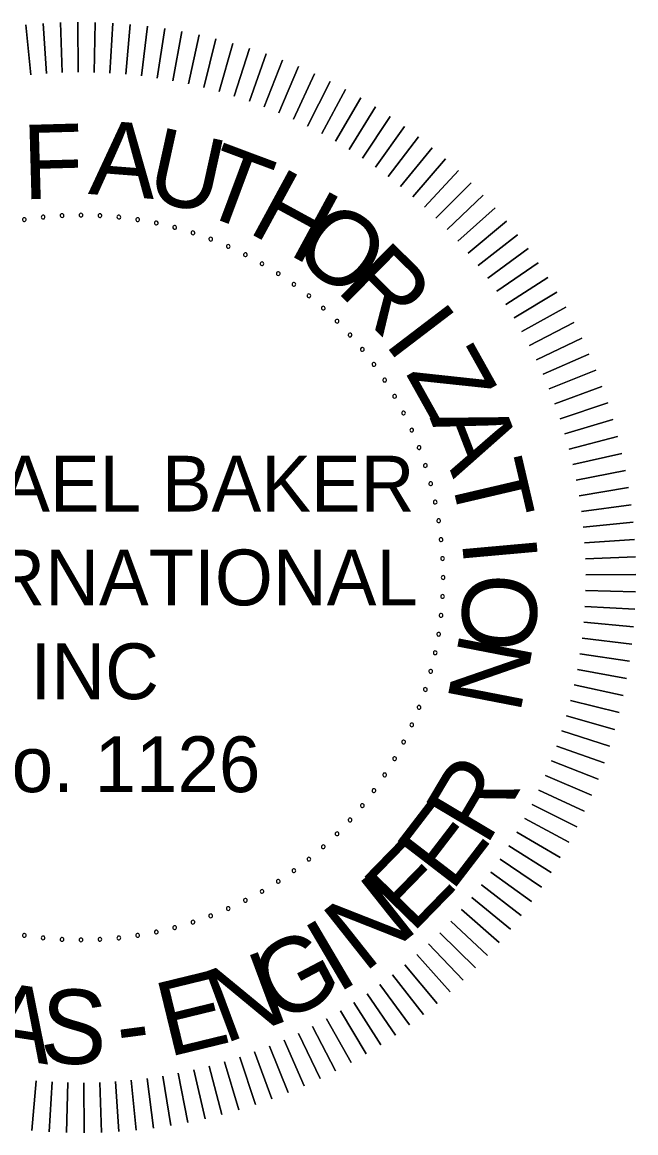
# Model space of a CAD drawing. Extents: x -24122 to 24238, y -8840 to 11381.
# Drawn here: x 11660 to 13036, y -8840 to -6351 of the extents above; entities that cross this region are included whole.
import ezdxf

# ---------------------------------------------------------------- set-up
doc = ezdxf.new("R2010")
doc.units = 0
doc.layers.add('G-ANNO-TEXT', color=7, linetype='Continuous')

msp = doc.modelspace()

# ---------------------------------------------------------------- linework, layer by layer
at = {"layer": 'G-ANNO-TEXT'}
for points in [[(11679.1, -6468.9), (11667.9, -6357.3)], [(11667.9, -6357.3), (11679.1, -6468.9)], [(11714.5, -6466), (11706.8, -6354)], [(11706.8, -6354), (11714.5, -6466)], [(11750, -6464.1), (11745.9, -6351.9)], [(11745.9, -6351.9), (11750, -6464.1)], [(11785.6, -6463.3), (11785, -6351.1)], [(11785, -6351.1), (11785.6, -6463.3)], [(11821.1, -6463.7), (11824, -6351.5)], [(11824, -6351.5), (11821.1, -6463.7)], [(11856.7, -6465.2), (11863.1, -6353.1)], [(11863.1, -6353.1), (11856.7, -6465.2)], [(11892.2, -6467.8), (11902.1, -6356)], [(11902.1, -6356), (11892.2, -6467.8)], [(11927.5, -6471.5), (11941, -6360)], [(11941, -6360), (11927.5, -6471.5)], [(11962.8, -6476.3), (11979.7, -6365.3)], [(11979.7, -6365.3), (11962.8, -6476.3)], [(11997.8, -6482.2), (12018.3, -6371.8)], [(12018.3, -6371.8), (11997.8, -6482.2)], [(12032.7, -6489.2), (12056.6, -6379.6)], [(12056.6, -6379.6), (12032.7, -6489.2)], [(12067.3, -6497.3), (12094.6, -6388.5)], [(12094.6, -6388.5), (12067.3, -6497.3)], [(12101.7, -6506.5), (12132.4, -6398.6)], [(12132.4, -6398.6), (12101.7, -6506.5)], [(12135.7, -6516.8), (12169.8, -6409.9)], [(12169.8, -6409.9), (12135.7, -6516.8)], [(12169.5, -6528.1), (12206.9, -6422.3)], [(12206.9, -6422.3), (12169.5, -6528.1)], [(12202.8, -6540.5), (12243.5, -6435.9)], [(12243.5, -6435.9), (12202.8, -6540.5)], [(12235.7, -6553.9), (12279.7, -6450.7)], [(12279.7, -6450.7), (12235.7, -6553.9)], [(12268.2, -6568.4), (12315.5, -6466.6)], [(12315.5, -6466.6), (12268.2, -6568.4)], [(12300.3, -6583.9), (12350.7, -6483.6)], [(12350.7, -6483.6), (12300.3, -6583.9)], [(12331.8, -6600.3), (12385.3, -6501.7)], [(12385.3, -6501.7), (12331.8, -6600.3)], [(12362.8, -6617.8), (12419.4, -6520.9)], [(12419.4, -6520.9), (12362.8, -6617.8)], [(12393.2, -6636.2), (12452.8, -6541.1)], [(12452.8, -6541.1), (12393.2, -6636.2)], [(12423, -6655.6), (12485.6, -6562.4)], [(12485.6, -6562.4), (12423, -6655.6)], [(12452.3, -6675.8), (12517.7, -6584.7)], [(12517.7, -6584.7), (12452.3, -6675.8)], [(12480.8, -6697), (12549.1, -6608)], [(12549.1, -6608), (12480.8, -6697)], [(12508.7, -6719.1), (12579.8, -6632.3)], [(12579.8, -6632.3), (12508.7, -6719.1)], [(12535.9, -6742.1), (12609.6, -6657.5)], [(12609.6, -6657.5), (12535.9, -6742.1)], [(12638.7, -6683.6), (12562.3, -6765.9)], [(12562.3, -6765.9), (12638.7, -6683.6)], [(12666.9, -6710.7), (12588, -6790.5)], [(12588, -6790.5), (12666.9, -6710.7)], [(12694.3, -6738.6), (12612.9, -6815.9)], [(12612.9, -6815.9), (12694.3, -6738.6)], [(12720.7, -6767.4), (12637, -6842)], [(12637, -6842), (12720.7, -6767.4)], [(12746.3, -6796.9), (12660.2, -6869)], [(12660.2, -6869), (12746.3, -6796.9)], [(12770.9, -6827.3), (12682.6, -6896.6)], [(12682.6, -6896.6), (12770.9, -6827.3)], [(12794.5, -6858.4), (12704.1, -6924.9)], [(12704.1, -6924.9), (12794.5, -6858.4)], [(12817.2, -6890.3), (12724.7, -6953.9)], [(12724.7, -6953.9), (12817.2, -6890.3)], [(12838.9, -6922.9), (12744.4, -6983.5)], [(12744.4, -6983.5), (12838.9, -6922.9)], [(12859.5, -6956.1), (12763.2, -7013.7)], [(12763.2, -7013.7), (12859.5, -6956.1)], [(12879, -6989.9), (12781, -7044.5)], [(12781, -7044.5), (12879, -6989.9)], [(12897.5, -7024.4), (12797.8, -7075.9)], [(12797.8, -7075.9), (12897.5, -7024.4)], [(12914.9, -7059.4), (12813.6, -7107.7)], [(12813.6, -7107.7), (12914.9, -7059.4)], [(12931.2, -7094.9), (12828.4, -7140.1)], [(12828.4, -7140.1), (12931.2, -7094.9)], [(12946.3, -7131), (12842.2, -7172.8)], [(12842.2, -7172.8), (12946.3, -7131)], [(12960.4, -7167.4), (12855, -7206)], [(12855, -7206), (12960.4, -7167.4)], [(12973.2, -7204.4), (12866.7, -7239.6)], [(12866.7, -7239.6), (12973.2, -7204.4)], [(12984.9, -7241.7), (12877.3, -7273.6)], [(12877.3, -7273.6), (12984.9, -7241.7)], [(12995.5, -7279.3), (12886.9, -7307.8)], [(12886.9, -7307.8), (12995.5, -7279.3)], [(13004.8, -7317.3), (12895.4, -7342.4)], [(12895.4, -7342.4), (13004.8, -7317.3)], [(13012.9, -7355.5), (12902.8, -7377.1)], [(12902.8, -7377.1), (13012.9, -7355.5)], [(13019.9, -7394), (12909.1, -7412.2)], [(12909.1, -7412.2), (13019.9, -7394)], [(13025.6, -7432.6), (12914.3, -7447.3)], [(12914.3, -7447.3), (13025.6, -7432.6)], [(13030.1, -7471.5), (12918.4, -7482.7)], [(12918.4, -7482.7), (13030.1, -7471.5)], [(13033.4, -7510.4), (12921.4, -7518.1)], [(12921.4, -7518.1), (13033.4, -7510.4)], [(13035.5, -7549.5), (12923.3, -7553.6)], [(12923.3, -7553.6), (13035.5, -7549.5)], [(13036.3, -7588.6), (12924.1, -7589.2)], [(12924.1, -7589.2), (13036.3, -7588.6)], [(13035.9, -7627.6), (12923.7, -7624.7)], [(12923.7, -7624.7), (13035.9, -7627.6)], [(13034.3, -7666.7), (12922.2, -7660.3)], [(12922.2, -7660.3), (13034.3, -7666.7)], [(13031.4, -7705.7), (12919.6, -7695.8)], [(12919.6, -7695.8), (13031.4, -7705.7)], [(13027.3, -7744.6), (12915.9, -7731.1)], [(12915.9, -7731.1), (13027.3, -7744.6)], [(13022, -7783.3), (12911.1, -7766.4)], [(12911.1, -7766.4), (13022, -7783.3)], [(13015.5, -7821.9), (12905.2, -7801.4)], [(12905.2, -7801.4), (13015.5, -7821.9)], [(13007.8, -7860.2), (12898.2, -7836.3)], [(12898.2, -7836.3), (13007.8, -7860.2)], [(12998.9, -7898.2), (12890.1, -7870.9)], [(12890.1, -7870.9), (12998.9, -7898.2)], [(12988.8, -7936), (12880.9, -7905.3)], [(12880.9, -7905.3), (12988.8, -7936)], [(12977.5, -7973.4), (12870.6, -7939.4)], [(12870.6, -7939.4), (12977.5, -7973.4)], [(12965.1, -8010.5), (12859.3, -7973.1)], [(12859.3, -7973.1), (12965.1, -8010.5)], [(12951.5, -8047.1), (12846.9, -8006.4)], [(12846.9, -8006.4), (12951.5, -8047.1)], [(12936.7, -8083.3), (12833.4, -8039.3)], [(12833.4, -8039.3), (12936.7, -8083.3)], [(12920.8, -8119.1), (12819, -8071.8)], [(12819, -8071.8), (12920.8, -8119.1)], [(12903.8, -8154.3), (12803.5, -8103.9)], [(12803.5, -8103.9), (12903.8, -8154.3)], [(12885.7, -8188.9), (12787.1, -8135.4)], [(12787.1, -8135.4), (12885.7, -8188.9)], [(12866.5, -8223), (12769.6, -8166.4)], [(12769.6, -8166.4), (12866.5, -8223)], [(12846.3, -8256.4), (12751.2, -8196.8)], [(12751.2, -8196.8), (12846.3, -8256.4)], [(12825, -8289.2), (12731.8, -8226.6)], [(12731.8, -8226.6), (12825, -8289.2)], [(12802.7, -8321.3), (12711.5, -8255.9)], [(12711.5, -8255.9), (12802.7, -8321.3)], [(12779.4, -8352.7), (12690.3, -8284.4)], [(12690.3, -8284.4), (12779.4, -8352.7)], [(12755.1, -8383.4), (12668.3, -8312.3)], [(12668.3, -8312.3), (12755.1, -8383.4)], [(12729.9, -8413.2), (12645.3, -8339.5)], [(12645.3, -8339.5), (12729.9, -8413.2)], [(12703.8, -8442.3), (12621.5, -8365.9)], [(12621.5, -8365.9), (12703.8, -8442.3)], [(12676.7, -8470.5), (12596.9, -8391.6)], [(12596.9, -8391.6), (12676.7, -8470.5)], [(12648.8, -8497.9), (12571.5, -8416.5)], [(12571.5, -8416.5), (12648.8, -8497.9)], [(12620, -8524.3), (12545.3, -8440.6)], [(12545.3, -8440.6), (12620, -8524.3)], [(12560.1, -8574.5), (12490.8, -8486.2)], [(12490.8, -8486.2), (12560.1, -8574.5)], [(12590.4, -8549.9), (12518.4, -8463.8)], [(12518.4, -8463.8), (12590.4, -8549.9)], [(12528.9, -8598.2), (12462.5, -8507.7)], [(12462.5, -8507.7), (12528.9, -8598.2)], [(12497.1, -8620.8), (12433.5, -8528.3)], [(12433.5, -8528.3), (12497.1, -8620.8)], [(12464.5, -8642.5), (12403.9, -8548)], [(12403.9, -8548), (12464.5, -8642.5)], [(12397.5, -8682.6), (12342.8, -8584.6)], [(12342.8, -8584.6), (12397.5, -8682.6)], [(12431.3, -8663.1), (12373.6, -8566.8)], [(12373.6, -8566.8), (12431.3, -8663.1)], [(12363, -8701.1), (12311.5, -8601.4)], [(12311.5, -8601.4), (12363, -8701.1)], [(12292.5, -8734.8), (12247.3, -8632)], [(12247.3, -8632), (12292.5, -8734.8)], [(12328, -8718.5), (12279.7, -8617.2)], [(12279.7, -8617.2), (12328, -8718.5)], [(12219.9, -8764), (12181.3, -8658.6)], [(12181.3, -8658.6), (12219.9, -8764)], [(12256.4, -8749.9), (12214.5, -8645.8)], [(12214.5, -8645.8), (12256.4, -8749.9)], [(12145.7, -8788.5), (12113.8, -8680.9)], [(12113.8, -8680.9), (12145.7, -8788.5)], [(12183, -8776.8), (12147.8, -8670.3)], [(12147.8, -8670.3), (12183, -8776.8)], [(12031.9, -8816.5), (12010.2, -8706.4)], [(12010.2, -8706.4), (12031.9, -8816.5)], [(12070.1, -8808.4), (12045, -8699)], [(12045, -8699), (12070.1, -8808.4)], [(12108.1, -8799.1), (12079.6, -8690.5)], [(12079.6, -8690.5), (12108.1, -8799.1)], [(11681.7, -8835), (11691.6, -8723.2)], [(11691.6, -8723.2), (11681.7, -8835)], [(11720.7, -8837.9), (11727.1, -8725.8)], [(11727.1, -8725.8), (11720.7, -8837.9)], [(11759.7, -8839.5), (11762.6, -8727.3)], [(11762.6, -8727.3), (11759.7, -8839.5)], [(11798.8, -8839.9), (11798.2, -8727.7)], [(11798.2, -8727.7), (11798.8, -8839.9)], [(11837.9, -8839.1), (11833.8, -8726.9)], [(11833.8, -8726.9), (11837.9, -8839.1)], [(11876.9, -8837), (11869.3, -8725)], [(11869.3, -8725), (11876.9, -8837)], [(11915.9, -8833.7), (11904.7, -8722)], [(11904.7, -8722), (11915.9, -8833.7)], [(11954.7, -8829.2), (11940, -8717.9)], [(11940, -8717.9), (11954.7, -8829.2)], [(11993.4, -8823.5), (11975.2, -8712.7)], [(11975.2, -8712.7), (11993.4, -8823.5)]]:
    msp.add_lwpolyline(points, dxfattribs=at)
for centre, start, end in [((11664.8, -6793.3), 9, 189), ((11664.8, -6793.3), 189, 9), ((11707, -6787.8), 6, 186), ((11707, -6787.8), 186, 6), ((11749.4, -6784.5), 3, 183), ((11749.4, -6784.5), 183, 3), ((11791.9, -6783.3), 0, 180), ((11791.9, -6783.3), 180, 0), ((11834.4, -6784.5), 357, 177), ((11834.4, -6784.5), 177, 357), ((11876.8, -6787.8), 354, 174), ((11876.8, -6787.8), 174, 354), ((11918.9, -6793.3), 351, 171), ((11918.9, -6793.3), 171, 351), ((11960.7, -6801.1), 168, 348), ((11960.7, -6801.1), 348, 168), ((12002.1, -6811), 165, 345), ((12002.1, -6811), 345, 165), ((12042.9, -6823.1), 342, 162), ((12042.9, -6823.1), 162, 342), ((12082.9, -6837.3), 159, 339), ((12082.9, -6837.3), 339, 159), ((12122.2, -6853.6), 156, 336), ((12122.2, -6853.6), 336, 156), ((12160.6, -6871.9), 333, 153), ((12160.6, -6871.9), 153, 333), ((12198, -6892.2), 150, 330), ((12198, -6892.2), 330, 150), ((12234.2, -6914.4), 147, 327), ((12234.2, -6914.4), 327, 147), ((12269.3, -6938.5), 144, 324), ((12269.3, -6938.5), 324, 144), ((12303, -6964.3), 141, 321), ((12303, -6964.3), 321, 141), ((12335.3, -6991.9), 138, 318), ((12335.3, -6991.9), 318, 138), ((12366.2, -7021.2), 135, 315), ((12366.2, -7021.2), 315, 135), ((12395.4, -7052.1), 132, 312), ((12395.4, -7052.1), 312, 132), ((12423, -7084.4), 129, 309), ((12423, -7084.4), 309, 129), ((12448.9, -7118.1), 126, 306), ((12448.9, -7118.1), 306, 126), ((12473, -7153.2), 123, 303), ((12473, -7153.2), 303, 123), ((12495.2, -7189.4), 120, 300), ((12495.2, -7189.4), 300, 120), ((12515.5, -7226.8), 117, 297), ((12515.5, -7226.8), 297, 117), ((12533.8, -7265.2), 114, 294), ((12533.8, -7265.2), 294, 114), ((12550.1, -7304.4), 111, 291), ((12550.1, -7304.4), 291, 111), ((12564.3, -7344.5), 108, 288), ((12564.3, -7344.5), 288, 108), ((12576.4, -7385.3), 105, 285), ((12576.4, -7385.3), 285, 105), ((12586.3, -7426.6), 102, 282), ((12586.3, -7426.6), 282, 102), ((12594, -7468.4), 99, 279), ((12594, -7468.4), 279, 99), ((12599.6, -7510.6), 96, 276), ((12599.6, -7510.6), 276, 96), ((12602.9, -7553), 93, 273), ((12602.9, -7553), 273, 93), ((12604, -7595.5), 90, 270), ((12604, -7595.5), 270, 90), ((12602.9, -7638), 87, 267), ((12602.9, -7638), 267, 87), ((12599.6, -7680.4), 84, 264), ((12599.6, -7680.4), 264, 84), ((12594, -7722.5), 81, 261), ((12594, -7722.5), 261, 81), ((12586.3, -7764.3), 78, 258), ((12586.3, -7764.3), 258, 78), ((12576.4, -7805.7), 75, 255), ((12576.4, -7805.7), 255, 75), ((12564.3, -7846.5), 72, 252), ((12564.3, -7846.5), 252, 72), ((12550.1, -7886.5), 69, 249), ((12550.1, -7886.5), 249, 69), ((12533.8, -7925.8), 66, 246), ((12533.8, -7925.8), 246, 66), ((12515.5, -7964.2), 63, 243), ((12515.5, -7964.2), 243, 63), ((12495.2, -8001.6), 60, 240), ((12495.2, -8001.6), 240, 60), ((12473, -8037.8), 57, 237), ((12473, -8037.8), 237, 57), ((12448.9, -8072.9), 54, 234), ((12448.9, -8072.9), 234, 54), ((12423, -8106.6), 51, 231), ((12423, -8106.6), 231, 51), ((12395.4, -8138.9), 48, 228), ((12395.4, -8138.9), 228, 48), ((12366.2, -8169.8), 45, 225), ((12366.2, -8169.8), 225, 45), ((12335.3, -8199), 42, 222), ((12335.3, -8199), 222, 42), ((12303, -8226.6), 39, 219), ((12303, -8226.6), 219, 39), ((12269.3, -8252.5), 36, 216), ((12269.3, -8252.5), 216, 36), ((12234.2, -8276.6), 33, 213), ((12234.2, -8276.6), 213, 33), ((12198, -8298.8), 30, 210), ((12198, -8298.8), 210, 30), ((12122.2, -8337.4), 24, 204), ((12122.2, -8337.4), 204, 24), ((12160.6, -8319.1), 27, 207), ((12160.6, -8319.1), 207, 27), ((12082.9, -8353.7), 21, 201), ((12082.9, -8353.7), 201, 21), ((11960.7, -8389.9), 12, 192), ((12002.1, -8380), 15, 195), ((12002.1, -8380), 195, 15), ((12042.9, -8367.9), 18, 198), ((12042.9, -8367.9), 198, 18), ((11664.8, -8397.6), 351, 171), ((11664.8, -8397.6), 171, 351), ((11707, -8403.2), 174, 354), ((11707, -8403.2), 354, 174), ((11749.4, -8406.5), 357, 177), ((11749.4, -8406.5), 177, 357), ((11791.9, -8407.6), 0, 180), ((11791.9, -8407.6), 180, 0), ((11834.4, -8406.5), 3, 183), ((11834.4, -8406.5), 183, 3), ((11876.8, -8403.2), 6, 186), ((11876.8, -8403.2), 186, 6), ((11918.9, -8397.6), 9, 189), ((11918.9, -8397.6), 189, 9), ((11960.7, -8389.9), 192, 12)]:
    msp.add_arc(centre, 4.17, start, end, dxfattribs=at)

# ---------------------------------------------------------------- texts
for s, rotation, p in [('F', 1.5867, (11662.6, -6748.2)), ('A', 355.5955, (11807.1, -6735.9)), ('U', 347.5481, (11933.2, -6747.8)), ('T', 339.5007, (12049.5, -6775.6)), ('H', 331.4533, (12162.6, -6820.2)), ('O', 323.4059, (12258.3, -6872.9)), ('R', 315.3585, (12361.5, -6951.9)), ('I', 307.3112, (12469.9, -7069.3)), ('Z', 299.2638, (12518.8, -7137.2)), ('A', 291.2164, (12573.5, -7237.5)), ('T', 283.169, (12617.1, -7355.4)), ('I', 275.1216, (12646, -7511.4)), ('O', 267.0743, (12651.8, -7583)), ('N', 259.0269, (12643.1, -7714.1)), ('R', 59.2262, (12700.6, -8199.9)), ('E', 52.4765, (12623.2, -8302.5)), ('E', 45.7268, (12534.4, -8395.3)), ('N', 38.4196, (12426.6, -8483.2)), ('I', 30.5495, (12366.1, -8529.2)), ('G', 27.7404, (12234.3, -8599.1)), ('N', 20.4332, (12113, -8641.2)), ('E', 13.6835, (11987.3, -8670.6)), ('A', 351.1991, (11571.4, -8664.3)), ('S', 357.9489, (11698.5, -8682.8)), ('-', 7.5077, (11880.4, -8683.2))]:
    msp.add_text(s, height=166.7, rotation=rotation, dxfattribs=at).set_placement(p)
for s, height, p in [('MICHAEL BAKER', 125.016, (11183.6, -7447.7)), (' INTERNATIONAL', 125.016, (11163.5, -7657.9)), ('INC', 125.02, (11678.7, -7868.2)), (' No. 1126', 125.02, (11469.2, -8076.5))]:
    msp.add_text(s, height=height, dxfattribs=at).set_placement(p)

doc.saveas('drawing.dxf')
